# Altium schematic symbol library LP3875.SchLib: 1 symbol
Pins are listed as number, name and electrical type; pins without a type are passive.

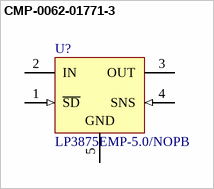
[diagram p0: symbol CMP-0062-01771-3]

## CMP-0062-01771-3
designator U?, comment LP3875EMP-5.0/NOPB
1.5A Fast Ultra Low Dropout Linear Regulator, 5-pin SOT-223, Pb-Free; Manufacturer: Texas Instruments; PowerWise: N; CompType: LDO IC; PackageTopMarking: XYTT*LHRB
footprint NDC0005A_M (SOT223, 5-Leads, Body 6.7x3.71mm, Pitch 1.5mm, IPC Low Density)
footprint NDC0005A_L (SOT223, 5-Leads, Body 6.7x3.71mm, Pitch 1.5mm, IPC High Density)
footprint NDC0005A_N (SOT223, 5-Leads, Body 6.7x3.71mm, Pitch 1.5mm, IPC Medium Density)
pins: 1 ~{SD} (in), 2 IN (power), 3 OUT (power), 4 SNS (in), 5 GND (power)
